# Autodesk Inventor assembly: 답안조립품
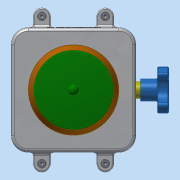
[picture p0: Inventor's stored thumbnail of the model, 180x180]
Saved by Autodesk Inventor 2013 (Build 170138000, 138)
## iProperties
Created: 2018-01
Part Number: 답안조립품
Document SubType Name: Assembly
Designer: dgall
Author: dgall
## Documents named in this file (9)
- C:\Users\dgall\Desktop\480107V1043\답안조립품.iam
- C:\Users\dgall\Desktop\480107V1043\답안본체.ipt
- C:\Users\dgall\Desktop\480107V1043\본체커버.ipt
- C:\Users\dgall\Desktop\480107V1043\볼트 M3x12.ipt
- C:\Users\dgall\Desktop\480107V1043\볼트 M4x12.ipt
- C:\Users\dgall\Desktop\480107V1043\용기.ipt
- C:\Users\dgall\Desktop\480107V1043\용기캡.ipt
- C:\Users\dgall\Desktop\480107V1043\핸들.ipt
- C:\Users\dgall\Desktop\480107V1043\핸들축.ipt
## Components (2 placed, 2 different names)
1. 핸들:1 — 각도:1
2. 핸들축:1 — 각도:1, 각도:2
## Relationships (2: Angle 2)
- 각도:1 [Angle]: 핸들:1 ↔ 핸들축:1
- 각도:2 [Angle]: 핸들축:1
